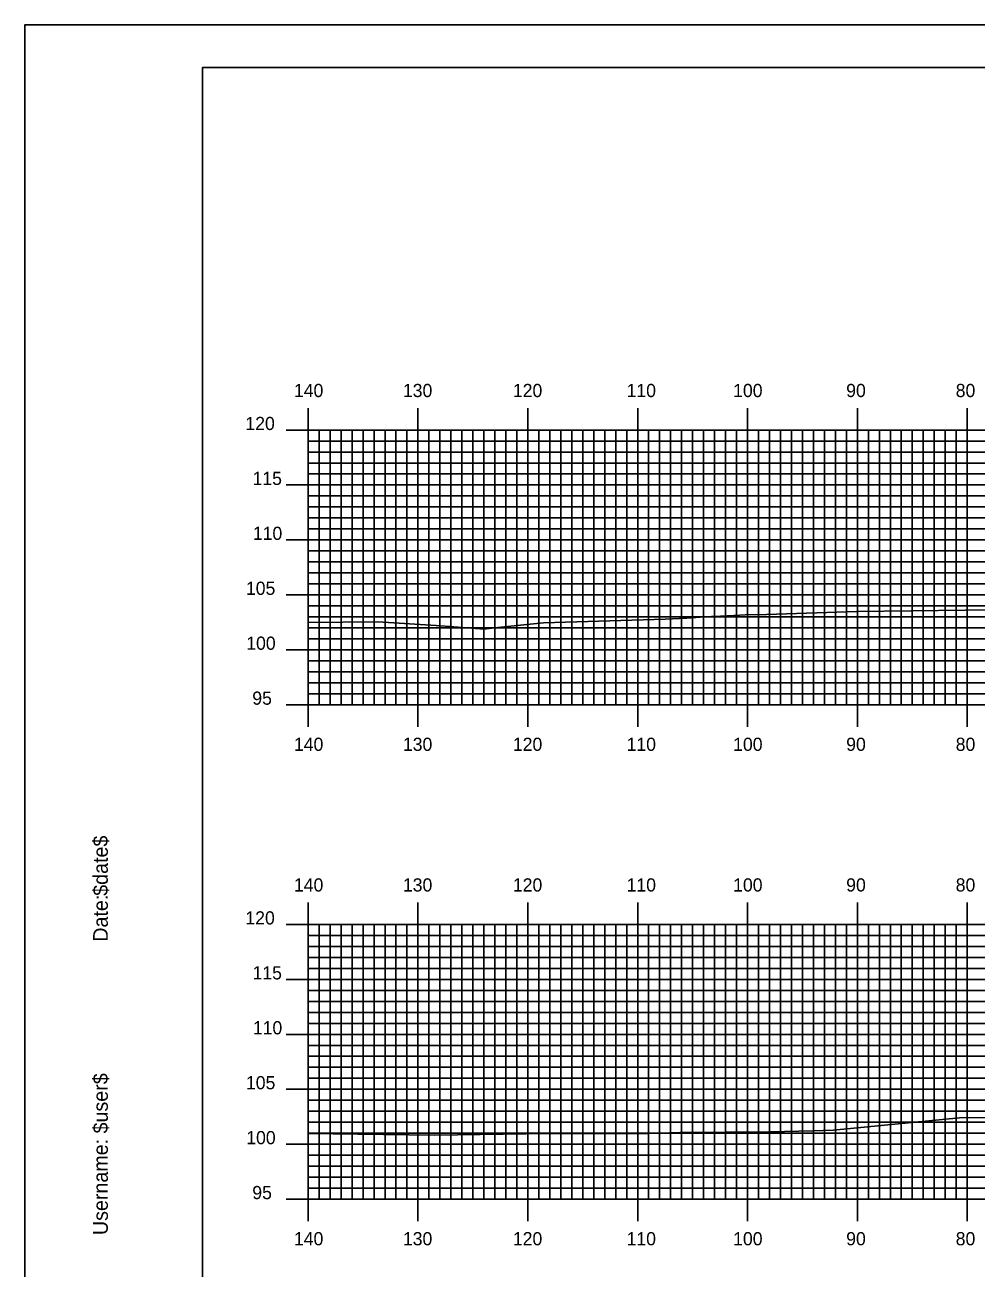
# Model space of a CAD drawing. Extents: x 1765726 to 1766069, y 442591 to 442811.
# Drawn here: x 1765726.1 to 1765812.7, y 442697.4 to 442810.5 of the extents above; entities that cross this region are included whole.
import ezdxf

# ---------------------------------------------------------------- set-up
doc = ezdxf.new("R2010")
doc.units = 0
for name, color, linetype in [('BORDER', 7, 'Continuous'), ('H_V ANNOTATION', 7, 'Continuous'), ('MAJOR', 7, 'Continuous'), ('MINOR', 7, 'Continuous'), ('PLOT BOUNDARY', 7, 'Continuous'), ('S_Roadway_Centerline', 7, 'Continuous')]:
    doc.layers.add(name, color=color, linetype=linetype)

msp = doc.modelspace()

# ---------------------------------------------------------------- linework, layer by layer
at = {"layer": 'BORDER'}
msp.add_lwpolyline([(1765742.28, 442596.67), (1766062.28, 442596.67), (1766062.28, 442806.67), (1765742.28, 442806.67)], close=True, dxfattribs=at)
at = {"layer": 'MAJOR'}
for p, q in [((1765751.88, 442775.67), (1765751.88, 442773.67)), ((1765761.88, 442775.67), (1765761.88, 442773.67)), ((1765771.88, 442775.67), (1765771.88, 442773.67)), ((1765781.88, 442775.67), (1765781.88, 442773.67)), ((1765791.88, 442775.67), (1765791.88, 442773.67)), ((1765801.88, 442775.67), (1765801.88, 442773.67)), ((1765811.88, 442775.67), (1765811.88, 442773.67)), ((1765749.88, 442773.67), (1765751.88, 442773.67)), ((1765751.88, 442773.67), (1766031.88, 442773.67)), ((1765751.88, 442748.67), (1765751.88, 442773.67)), ((1765751.88, 442748.67), (1765751.88, 442773.67)), ((1765751.88, 442773.67), (1766031.88, 442773.67)), ((1765761.88, 442748.67), (1765761.88, 442773.67)), ((1765771.88, 442748.67), (1765771.88, 442773.67)), ((1765781.88, 442748.67), (1765781.88, 442773.67)), ((1765791.88, 442748.67), (1765791.88, 442773.67)), ((1765801.88, 442748.67), (1765801.88, 442773.67)), ((1765811.88, 442748.67), (1765811.88, 442773.67)), ((1765749.88, 442768.67), (1765751.88, 442768.67)), ((1765751.88, 442768.67), (1766031.88, 442768.67)), ((1765749.88, 442763.67), (1765751.88, 442763.67)), ((1765751.88, 442763.67), (1766031.88, 442763.67)), ((1765749.88, 442758.67), (1765751.88, 442758.67)), ((1765751.88, 442758.67), (1766031.88, 442758.67)), ((1765749.88, 442753.67), (1765751.88, 442753.67)), ((1765751.88, 442753.67), (1766031.88, 442753.67)), ((1765749.88, 442748.67), (1765751.88, 442748.67)), ((1765751.88, 442748.67), (1766031.88, 442748.67)), ((1765751.88, 442748.67), (1766031.88, 442748.67)), ((1765751.88, 442746.66), (1765751.88, 442748.67)), ((1765761.88, 442746.66), (1765761.88, 442748.67)), ((1765771.88, 442746.66), (1765771.88, 442748.67)), ((1765781.88, 442746.66), (1765781.88, 442748.67)), ((1765791.88, 442746.66), (1765791.88, 442748.67)), ((1765801.88, 442746.66), (1765801.88, 442748.67)), ((1765811.88, 442746.66), (1765811.88, 442748.67)), ((1765751.88, 442730.67), (1765751.88, 442728.67)), ((1765761.88, 442730.67), (1765761.88, 442728.67)), ((1765771.88, 442730.67), (1765771.88, 442728.67)), ((1765781.88, 442730.67), (1765781.88, 442728.67)), ((1765791.88, 442730.67), (1765791.88, 442728.67)), ((1765801.88, 442730.67), (1765801.88, 442728.67)), ((1765811.88, 442730.67), (1765811.88, 442728.67)), ((1765749.88, 442728.67), (1765751.88, 442728.67)), ((1765751.88, 442728.67), (1766031.88, 442728.67)), ((1765751.88, 442703.67), (1765751.88, 442728.67)), ((1765751.88, 442703.67), (1765751.88, 442728.67)), ((1765751.88, 442728.67), (1766031.88, 442728.67)), ((1765761.88, 442703.67), (1765761.88, 442728.67)), ((1765771.88, 442703.67), (1765771.88, 442728.67)), ((1765781.88, 442703.67), (1765781.88, 442728.67)), ((1765791.88, 442703.67), (1765791.88, 442728.67)), ((1765801.88, 442703.67), (1765801.88, 442728.67)), ((1765811.88, 442703.67), (1765811.88, 442728.67)), ((1765749.88, 442723.67), (1765751.88, 442723.67)), ((1765751.88, 442723.67), (1766031.88, 442723.67)), ((1765749.88, 442718.67), (1765751.88, 442718.67)), ((1765751.88, 442718.67), (1766031.88, 442718.67)), ((1765749.88, 442713.67), (1765751.88, 442713.67)), ((1765751.88, 442713.67), (1766031.88, 442713.67)), ((1765749.88, 442708.67), (1765751.88, 442708.67)), ((1765751.88, 442708.67), (1766031.88, 442708.67)), ((1765749.88, 442703.67), (1765751.88, 442703.67)), ((1765751.88, 442703.67), (1766031.88, 442703.67)), ((1765751.88, 442703.67), (1766031.88, 442703.67)), ((1765751.88, 442701.66), (1765751.88, 442703.67)), ((1765761.88, 442701.66), (1765761.88, 442703.67)), ((1765771.88, 442701.66), (1765771.88, 442703.67)), ((1765781.88, 442701.66), (1765781.88, 442703.67)), ((1765791.88, 442701.66), (1765791.88, 442703.67)), ((1765801.88, 442701.66), (1765801.88, 442703.67)), ((1765811.88, 442701.66), (1765811.88, 442703.67))]:
    msp.add_line(p, q, dxfattribs=at)
at = {"layer": 'MINOR'}
for p, q in [((1765751.88, 442772.67), (1766031.88, 442772.67)), ((1765751.88, 442772.67), (1765753.89, 442772.67)), ((1765752.88, 442748.67), (1765752.88, 442773.67)), ((1765753.88, 442748.67), (1765753.88, 442773.67)), ((1765754.88, 442748.67), (1765754.88, 442773.67)), ((1765755.88, 442748.67), (1765755.88, 442773.67)), ((1765756.88, 442748.67), (1765756.88, 442773.67)), ((1765757.88, 442748.67), (1765757.88, 442773.67)), ((1765758.88, 442748.67), (1765758.88, 442773.67)), ((1765759.88, 442748.67), (1765759.88, 442773.67)), ((1765760.88, 442748.67), (1765760.88, 442773.67)), ((1765762.88, 442748.67), (1765762.88, 442773.67)), ((1765763.88, 442748.67), (1765763.88, 442773.67)), ((1765764.88, 442748.67), (1765764.88, 442773.67)), ((1765765.88, 442748.67), (1765765.88, 442773.67)), ((1765766.88, 442748.67), (1765766.88, 442773.67)), ((1765767.88, 442748.67), (1765767.88, 442773.67)), ((1765768.88, 442748.67), (1765768.88, 442773.67)), ((1765769.88, 442748.67), (1765769.88, 442773.67)), ((1765770.88, 442748.67), (1765770.88, 442773.67)), ((1765772.88, 442748.67), (1765772.88, 442773.67)), ((1765773.88, 442748.67), (1765773.88, 442773.67)), ((1765774.88, 442748.67), (1765774.88, 442773.67)), ((1765775.88, 442748.67), (1765775.88, 442773.67)), ((1765776.88, 442748.67), (1765776.88, 442773.67)), ((1765777.88, 442748.67), (1765777.88, 442773.67)), ((1765778.88, 442748.67), (1765778.88, 442773.67)), ((1765779.88, 442748.67), (1765779.88, 442773.67)), ((1765780.88, 442748.67), (1765780.88, 442773.67)), ((1765782.88, 442748.67), (1765782.88, 442773.67)), ((1765783.88, 442748.67), (1765783.88, 442773.67)), ((1765784.88, 442748.67), (1765784.88, 442773.67)), ((1765785.88, 442748.67), (1765785.88, 442773.67)), ((1765786.88, 442748.67), (1765786.88, 442773.67)), ((1765787.88, 442748.67), (1765787.88, 442773.67)), ((1765788.88, 442748.67), (1765788.88, 442773.67)), ((1765789.88, 442748.67), (1765789.88, 442773.67)), ((1765790.88, 442748.67), (1765790.88, 442773.67)), ((1765792.88, 442748.67), (1765792.88, 442773.67)), ((1765793.88, 442748.67), (1765793.88, 442773.67)), ((1765794.88, 442748.67), (1765794.88, 442773.67)), ((1765795.88, 442748.67), (1765795.88, 442773.67)), ((1765796.88, 442748.67), (1765796.88, 442773.67)), ((1765797.88, 442748.67), (1765797.88, 442773.67)), ((1765798.88, 442748.67), (1765798.88, 442773.67)), ((1765799.88, 442748.67), (1765799.88, 442773.67)), ((1765800.88, 442748.67), (1765800.88, 442773.67)), ((1765802.88, 442748.67), (1765802.88, 442773.67)), ((1765803.88, 442748.67), (1765803.88, 442773.67)), ((1765804.88, 442748.67), (1765804.88, 442773.67)), ((1765805.88, 442748.67), (1765805.88, 442773.67)), ((1765806.88, 442748.67), (1765806.88, 442773.67)), ((1765807.88, 442748.67), (1765807.88, 442773.67)), ((1765808.88, 442748.67), (1765808.88, 442773.67)), ((1765809.88, 442748.67), (1765809.88, 442773.67)), ((1765810.88, 442748.67), (1765810.88, 442773.67)), ((1765751.88, 442771.67), (1766031.88, 442771.67)), ((1765751.88, 442771.67), (1765753.89, 442771.67)), ((1765751.88, 442770.67), (1766031.88, 442770.67)), ((1765751.88, 442770.67), (1765753.89, 442770.67)), ((1765751.88, 442769.67), (1766031.88, 442769.67)), ((1765751.88, 442769.67), (1765753.89, 442769.67)), ((1765751.88, 442767.67), (1766031.88, 442767.67)), ((1765751.88, 442767.67), (1765753.89, 442767.67)), ((1765751.88, 442766.67), (1766031.88, 442766.67)), ((1765751.88, 442766.67), (1765753.89, 442766.67)), ((1765751.88, 442765.67), (1766031.88, 442765.67)), ((1765751.88, 442765.67), (1765753.89, 442765.67)), ((1765751.88, 442764.67), (1766031.88, 442764.67)), ((1765751.88, 442764.67), (1765753.89, 442764.67)), ((1765751.88, 442762.67), (1766031.88, 442762.67)), ((1765751.88, 442762.67), (1765753.89, 442762.67)), ((1765751.88, 442761.67), (1766031.88, 442761.67)), ((1765751.88, 442761.67), (1765753.89, 442761.67)), ((1765751.88, 442760.67), (1766031.88, 442760.67)), ((1765751.88, 442760.67), (1765753.89, 442760.67)), ((1765751.88, 442759.67), (1766031.88, 442759.67)), ((1765751.88, 442759.67), (1765753.89, 442759.67)), ((1765751.88, 442757.67), (1766031.88, 442757.67)), ((1765751.88, 442757.67), (1765753.89, 442757.67)), ((1765751.88, 442756.67), (1766031.88, 442756.67)), ((1765751.88, 442756.67), (1765753.89, 442756.67)), ((1765751.88, 442755.67), (1766031.88, 442755.67)), ((1765751.88, 442755.67), (1765753.89, 442755.67)), ((1765751.88, 442754.67), (1766031.88, 442754.67)), ((1765751.88, 442754.67), (1765753.89, 442754.67)), ((1765751.88, 442752.67), (1766031.88, 442752.67)), ((1765751.88, 442752.67), (1765753.89, 442752.67)), ((1765751.88, 442751.67), (1766031.88, 442751.67)), ((1765751.88, 442751.67), (1765753.89, 442751.67)), ((1765751.88, 442750.67), (1766031.88, 442750.67)), ((1765751.88, 442750.67), (1765753.89, 442750.67)), ((1765751.88, 442749.67), (1766031.88, 442749.67)), ((1765751.88, 442749.67), (1765753.89, 442749.67)), ((1765752.88, 442703.67), (1765752.88, 442728.67)), ((1765753.88, 442703.67), (1765753.88, 442728.67)), ((1765754.88, 442703.67), (1765754.88, 442728.67)), ((1765755.88, 442703.67), (1765755.88, 442728.67)), ((1765756.88, 442703.67), (1765756.88, 442728.67)), ((1765757.88, 442703.67), (1765757.88, 442728.67)), ((1765758.88, 442703.67), (1765758.88, 442728.67)), ((1765759.88, 442703.67), (1765759.88, 442728.67)), ((1765760.88, 442703.67), (1765760.88, 442728.67)), ((1765762.88, 442703.67), (1765762.88, 442728.67)), ((1765763.88, 442703.67), (1765763.88, 442728.67)), ((1765764.88, 442703.67), (1765764.88, 442728.67)), ((1765765.88, 442703.67), (1765765.88, 442728.67)), ((1765766.88, 442703.67), (1765766.88, 442728.67)), ((1765767.88, 442703.67), (1765767.88, 442728.67)), ((1765768.88, 442703.67), (1765768.88, 442728.67)), ((1765769.88, 442703.67), (1765769.88, 442728.67)), ((1765770.88, 442703.67), (1765770.88, 442728.67)), ((1765772.88, 442703.67), (1765772.88, 442728.67)), ((1765773.88, 442703.67), (1765773.88, 442728.67)), ((1765774.88, 442703.67), (1765774.88, 442728.67)), ((1765775.88, 442703.67), (1765775.88, 442728.67)), ((1765776.88, 442703.67), (1765776.88, 442728.67)), ((1765777.88, 442703.67), (1765777.88, 442728.67)), ((1765778.88, 442703.67), (1765778.88, 442728.67)), ((1765779.88, 442703.67), (1765779.88, 442728.67)), ((1765780.88, 442703.67), (1765780.88, 442728.67)), ((1765782.88, 442703.67), (1765782.88, 442728.67)), ((1765783.88, 442703.67), (1765783.88, 442728.67)), ((1765784.88, 442703.67), (1765784.88, 442728.67)), ((1765785.88, 442703.67), (1765785.88, 442728.67)), ((1765786.88, 442703.67), (1765786.88, 442728.67)), ((1765787.88, 442703.67), (1765787.88, 442728.67)), ((1765788.88, 442703.67), (1765788.88, 442728.67)), ((1765789.88, 442703.67), (1765789.88, 442728.67)), ((1765790.88, 442703.67), (1765790.88, 442728.67)), ((1765792.88, 442703.67), (1765792.88, 442728.67)), ((1765793.88, 442703.67), (1765793.88, 442728.67)), ((1765794.88, 442703.67), (1765794.88, 442728.67)), ((1765795.88, 442703.67), (1765795.88, 442728.67)), ((1765796.88, 442703.67), (1765796.88, 442728.67)), ((1765797.88, 442703.67), (1765797.88, 442728.67)), ((1765798.88, 442703.67), (1765798.88, 442728.67)), ((1765799.88, 442703.67), (1765799.88, 442728.67)), ((1765800.88, 442703.67), (1765800.88, 442728.67)), ((1765802.88, 442703.67), (1765802.88, 442728.67)), ((1765803.88, 442703.67), (1765803.88, 442728.67)), ((1765804.88, 442703.67), (1765804.88, 442728.67)), ((1765805.88, 442703.67), (1765805.88, 442728.67)), ((1765806.88, 442703.67), (1765806.88, 442728.67)), ((1765807.88, 442703.67), (1765807.88, 442728.67)), ((1765808.88, 442703.67), (1765808.88, 442728.67)), ((1765809.88, 442703.67), (1765809.88, 442728.67)), ((1765810.88, 442703.67), (1765810.88, 442728.67)), ((1765751.88, 442727.67), (1766031.88, 442727.67)), ((1765751.88, 442727.67), (1765753.89, 442727.67)), ((1765751.88, 442726.67), (1766031.88, 442726.67)), ((1765751.88, 442726.67), (1765753.89, 442726.67)), ((1765751.88, 442725.67), (1766031.88, 442725.67)), ((1765751.88, 442725.67), (1765753.89, 442725.67)), ((1765751.88, 442724.67), (1766031.88, 442724.67)), ((1765751.88, 442724.67), (1765753.89, 442724.67)), ((1765751.88, 442722.67), (1766031.88, 442722.67)), ((1765751.88, 442722.67), (1765753.89, 442722.67)), ((1765751.88, 442721.67), (1766031.88, 442721.67)), ((1765751.88, 442721.67), (1765753.89, 442721.67)), ((1765751.88, 442720.67), (1766031.88, 442720.67)), ((1765751.88, 442720.67), (1765753.89, 442720.67)), ((1765751.88, 442719.67), (1766031.88, 442719.67)), ((1765751.88, 442719.67), (1765753.89, 442719.67)), ((1765751.88, 442717.67), (1766031.88, 442717.67)), ((1765751.88, 442717.67), (1765753.89, 442717.67)), ((1765751.88, 442716.67), (1766031.88, 442716.67)), ((1765751.88, 442716.67), (1765753.89, 442716.67)), ((1765751.88, 442715.67), (1766031.88, 442715.67)), ((1765751.88, 442715.67), (1765753.89, 442715.67)), ((1765751.88, 442714.67), (1766031.88, 442714.67)), ((1765751.88, 442714.67), (1765753.89, 442714.67)), ((1765751.88, 442712.67), (1766031.88, 442712.67)), ((1765751.88, 442712.67), (1765753.89, 442712.67)), ((1765751.88, 442711.67), (1766031.88, 442711.67)), ((1765751.88, 442711.67), (1765753.89, 442711.67)), ((1765751.88, 442710.67), (1766031.88, 442710.67)), ((1765751.88, 442710.67), (1765753.89, 442710.67)), ((1765751.88, 442709.67), (1766031.88, 442709.67)), ((1765751.88, 442709.67), (1765753.89, 442709.67)), ((1765751.88, 442707.67), (1766031.88, 442707.67)), ((1765751.88, 442707.67), (1765753.89, 442707.67)), ((1765751.88, 442706.67), (1766031.88, 442706.67)), ((1765751.88, 442706.67), (1765753.89, 442706.67)), ((1765751.88, 442705.67), (1766031.88, 442705.67)), ((1765751.88, 442705.67), (1765753.89, 442705.67)), ((1765751.88, 442704.67), (1766031.88, 442704.67)), ((1765751.88, 442704.67), (1765753.89, 442704.67))]:
    msp.add_line(p, q, dxfattribs=at)
at = {"layer": 'PLOT BOUNDARY'}
msp.add_lwpolyline([(1765726.1, 442590.55), (1766066.1, 442590.55), (1766066.1, 442810.55), (1765726.1, 442810.55)], close=True, dxfattribs=at)
at = {"layer": 'S_Roadway_Centerline'}
for points in [[(1765751.88, 442756.16), (1765758.23, 442756.22), (1765763.55, 442755.89), (1765766.74, 442755.65), (1765767.88, 442755.56), (1765768.86, 442755.66), (1765770.63, 442755.84), (1765772.1, 442755.99), (1765773.32, 442756.11), (1765784.39, 442756.47), (1765786.36, 442756.54), (1765787.58, 442756.64), (1765788.61, 442756.7), (1765789.41, 442756.74), (1765790.04, 442756.77), (1765790.62, 442756.8), (1765791.17, 442756.83), (1765791.68, 442756.85), (1765793.62, 442756.88), (1765801.84, 442757.15), (1765811.71, 442757.29), (1765815.32, 442757.33)], [(1765751.88, 442709.65), (1765756.4, 442709.6), (1765761.04, 442709.52), (1765763.42, 442709.49), (1765773.77, 442709.66), (1765781.88, 442709.63), (1765785.73, 442709.74), (1765793.98, 442709.81), (1765797.81, 442709.88), (1765799.72, 442709.95), (1765811.19, 442711.08), (1765818.21, 442711.14)]]:
    msp.add_lwpolyline(points, dxfattribs=at)

# ---------------------------------------------------------------- texts
at = {"layer": 'BORDER'}
for s, p in [('$date$', (1765733.65, 442731.28)), ('Date:', (1765733.65, 442727.1)), ('$user$', (1765733.65, 442709.65)), ('Username:', (1765733.65, 442700.4))]:
    msp.add_text(s, height=1.339, rotation=90, dxfattribs=at).set_placement(p)
at = {"layer": 'H_V ANNOTATION'}
for s, p in [('140', (1765750.59, 442776.67)), ('130', (1765760.51, 442776.67)), ('120', (1765770.52, 442776.67)), ('110', (1765780.87, 442776.67)), ('100', (1765790.57, 442776.67)), ('90', (1765800.86, 442776.67)), ('80', (1765810.83, 442776.67)), ('120', (1765746.17, 442773.67)), ('115', (1765746.82, 442768.67)), ('110', (1765746.85, 442763.67)), ('105', (1765746.22, 442758.67)), ('100', (1765746.25, 442753.67)), ('95', (1765746.8, 442748.67)), ('140', (1765750.59, 442744.47)), ('130', (1765760.51, 442744.47)), ('120', (1765770.52, 442744.47)), ('110', (1765780.87, 442744.47)), ('100', (1765790.57, 442744.47)), ('90', (1765800.86, 442744.47)), ('80', (1765810.83, 442744.47)), ('140', (1765750.59, 442731.67)), ('130', (1765760.51, 442731.67)), ('120', (1765770.52, 442731.67)), ('110', (1765780.87, 442731.67)), ('100', (1765790.57, 442731.67)), ('90', (1765800.86, 442731.67)), ('80', (1765810.83, 442731.67)), ('120', (1765746.17, 442728.67)), ('115', (1765746.82, 442723.67)), ('110', (1765746.85, 442718.67)), ('105', (1765746.22, 442713.67)), ('100', (1765746.25, 442708.67)), ('95', (1765746.8, 442703.67)), ('140', (1765750.59, 442699.47)), ('130', (1765760.51, 442699.47)), ('120', (1765770.52, 442699.47)), ('110', (1765780.87, 442699.47)), ('100', (1765790.57, 442699.47)), ('90', (1765800.86, 442699.47)), ('80', (1765810.83, 442699.47))]:
    msp.add_text(s, height=1.2, dxfattribs=at).set_placement(p)
at = {"layer": 'MAJOR'}
for p in [(1765751.88, 442748.67), (1765751.88, 442703.67)]:
    msp.add_text('-', height=0.012, dxfattribs=at).set_placement(p)

doc.saveas('drawing.dxf')
